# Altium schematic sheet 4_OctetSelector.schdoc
size 309 x 223 mm; Symbol: Sheet-Symbol_A4; Device: Sheet-Symbol_A4; @Project Name: Actuator Module; @Page Count: 5; @Update Date: 2024-10-20; @Create Date: 2024-10-21; @Schematic Name: Schematic-A_2; @Page No: 4; @Page Name: OctetSelector; Company: EasyEDA.com; Reviewed: EasyEDA; Version: V0.1; Page Size: A4; Part Number: JLCPCB-002; Drawn: EasyEDA; @Board Name: BaseModule; @Create Time: 01:40:53; @Update Time: 21:40:55
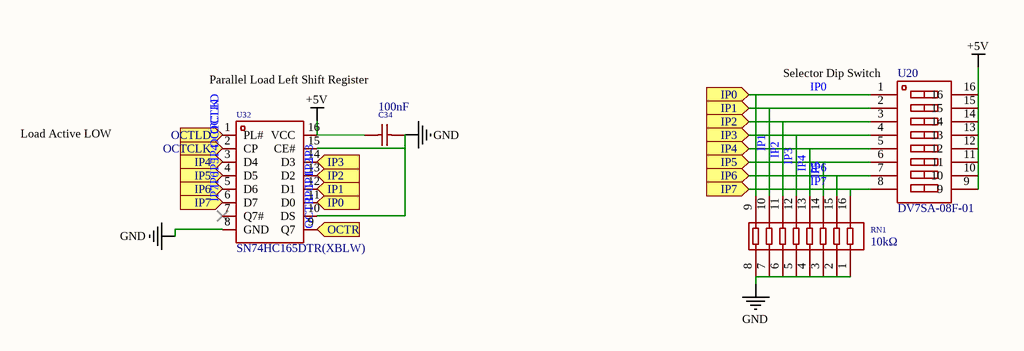
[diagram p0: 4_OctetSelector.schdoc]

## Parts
C34  100nF  [C0805]
RN1  10kΩ  [RES-ARRAY-SMD_16P-L3.8-W1.6-P0.50-BL]
U20  DV7SA-08F-01  [SW-SMD_DV7SA-08F-01]
U32  SN74HC165DTR(XBLW)  [SOP-16_L9.9-W3.9-P1.27-LS6.0-BL]

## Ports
IP0 (in), IP1 (in), IP2 (in), IP3 (in), IP4 (in), IP5 (in), IP6 (in), IP7 (in), OCTCLK (in), OCTLD (in), OCTR (in)

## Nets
+5V: C34.2 U20.9 U20.10 U20.11 U20.12 U20.13 U20.14 U20.15 U20.16 U32.16(VCC)
GND: C34.1 RN1.1 RN1.2 RN1.3 RN1.4 RN1.5 RN1.6 RN1.7 RN1.8 U32.8(GND) U32.10(DS) U32.15(CE#)
IP0: RN1.9 U20.1 U32.11(D0) ; port IP0
IP1: RN1.10 U20.2 U32.12(D1) ; port IP1
IP2: RN1.11 U20.3 U32.13(D2) ; port IP2
IP3: RN1.12 U20.4 U32.14(D3) ; port IP3
IP4: RN1.13 RN1.15 RN1.16 U20.5 U20.7 U20.8 U32.3(D4) U32.5(D6) U32.6(D7) ; port IP4, port IP6, port IP7  [also labelled IP6, IP7]
IP5: RN1.14 U20.6 U32.4(D5) ; port IP5
OCTCLK: U32.2(CP) ; port OCTCLK
OCTLD: U32.1(PL#) ; port OCTLD
OCTR: U32.9(Q7) ; port OCTR

Not connected (* = marked no-connect by the designer): U32 7(Q7#)*

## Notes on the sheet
- Parallel Load Left Shift Register
- (near U20) Selector Dip Switch
- Load Active LOW

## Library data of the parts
C34 = 0805B104K500NT: Manufacturer: FH(风华); Add into BOM: yes; Tolerance: ±10%
RN1 = EXB2HV103JV: Manufacturer: PANASONIC(松下); Add into BOM: yes; Tolerance: ±5%; Temperature Coefficient: ±200ppm/℃
U20 = DV7SA-08F-01: Manufacturer: G-Switch(品赞); Add into BOM: yes; Circuit: SPST; Number of Positions: 8-bit
U32 = SN74HC165DTR(XBLW): Manufacturer: XBLW(芯伯乐); Add into BOM: yes; Supply Voltage: 2V~6V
